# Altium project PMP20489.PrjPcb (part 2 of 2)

## Sheet PMP20489_outputs_dynLoad_Bias_HDWR.SchDoc
size 431 x 279 mm; Date: Not shown in title block; ApprovedBy: Not shown in title block; CheckedBy: Not shown in title block; Author: Not shown in title block; CompanyName: Not shown in title block; Engineer: Not shown in title block; Organization: Not shown in title block; Address1: Not shown in title block; Address2: Not shown in title block; Address3: Not shown in title block; Address4: Not shown in title block; DocumentNumber: 4; Revision: Use project parameter SCH_Rev; SheetNumber: 4; SheetTotal: 4; PageSetup: Record=PageOptions¦CenterHorizontal=True¦CenterVertical=True¦PrintScale=1.00¦XCorrection=1.00¦YCorrection=1.00¦PrintKind=0¦BorderSize=5000000¦LeftOffset=0¦BottomOffset=0¦Orientation=2¦PaperLength=1000¦PaperWidth=1000¦Scale=100¦PaperSource=15¦PrintQuality=600¦MediaType=1¦DitherType=10¦PaperKind=Letter¦PrintScaleMode=1
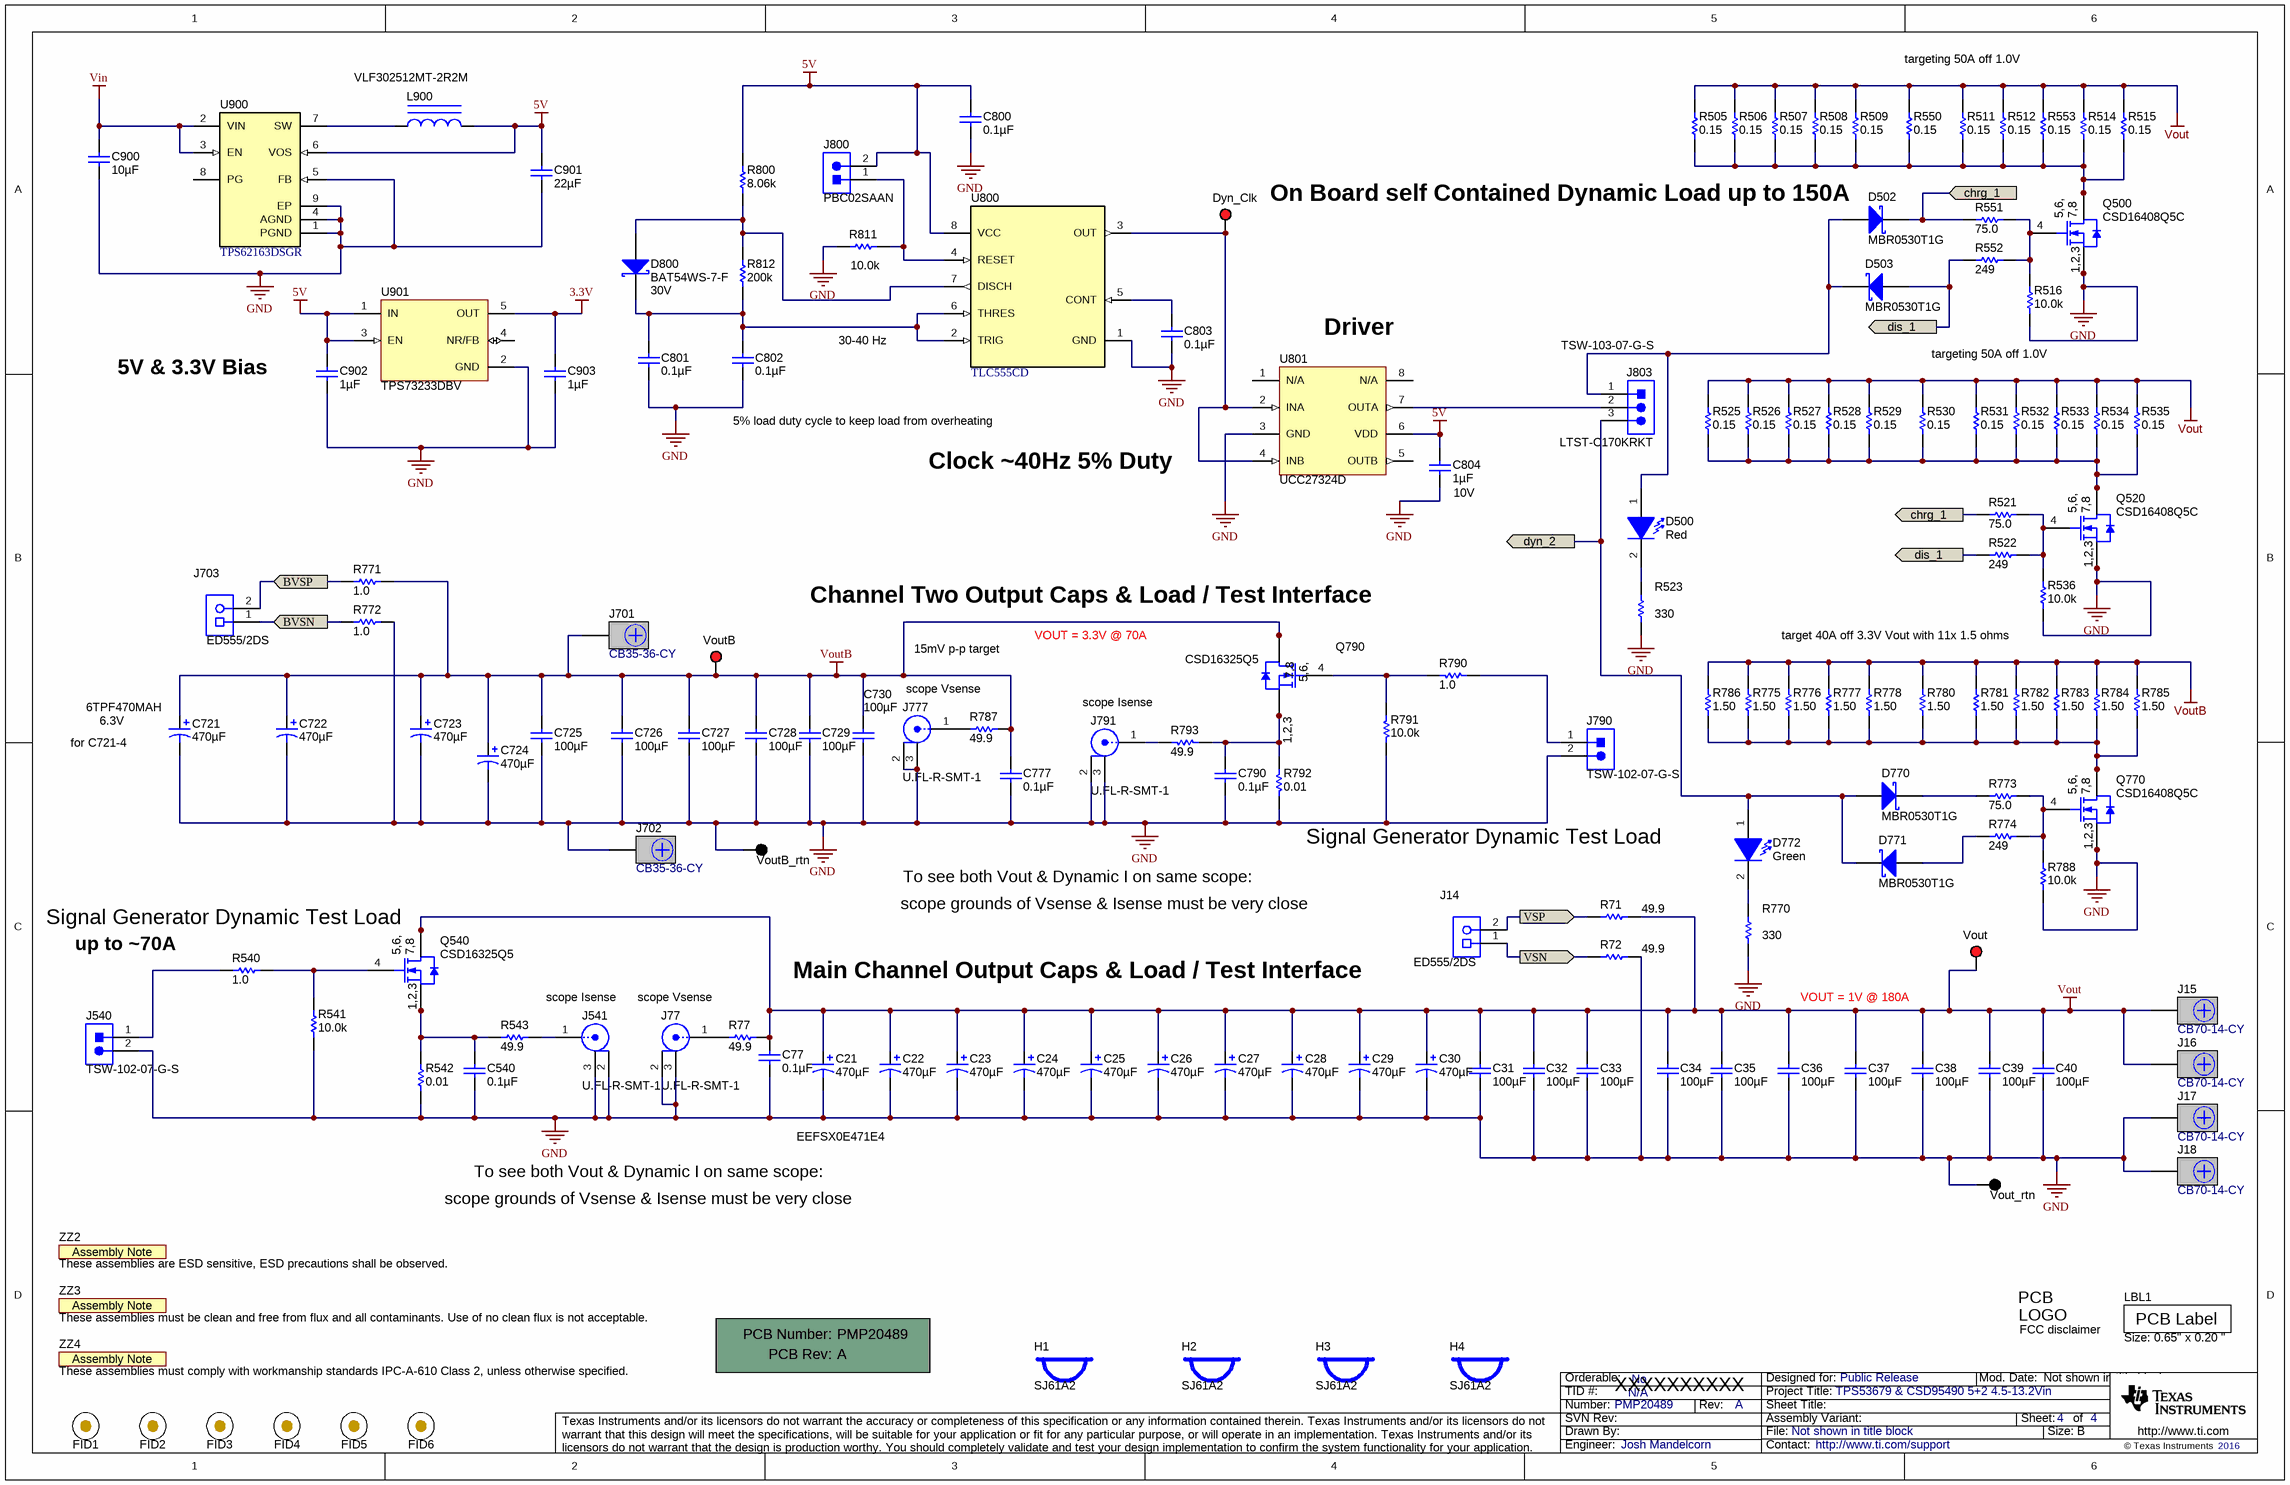
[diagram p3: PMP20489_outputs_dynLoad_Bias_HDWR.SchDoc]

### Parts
!PCB1  Printed Circuit Board  (value not drawn)  (mechanical)
C21  EEFSX0E471E4  ValueDisplayed: 470µF  [SP-Cap_Standard]
C22  ValueDisplayed: 470µF  [SP-Cap_Standard]  (hidden comment: EEFSX0E471E4)
C23  ValueDisplayed: 470µF  [SP-Cap_Standard]  (hidden comment: EEFSX0E471E4)
C24  ValueDisplayed: 470µF  [SP-Cap_Standard]  (hidden comment: EEFSX0E471E4)
C25  ValueDisplayed: 470µF  [SP-Cap_Standard]  (hidden comment: EEFSX0E471E4)
C26  ValueDisplayed: 470µF  [SP-Cap_Standard]  (hidden comment: EEFSX0E471E4)
C27  ValueDisplayed: 470µF  [SP-Cap_Standard]  (hidden comment: EEFSX0E471E4)
C28  ValueDisplayed: 470µF  [SP-Cap_Standard]  (hidden comment: EEFSX0E471E4)
C29  ValueDisplayed: 470µF  [SP-Cap_Standard]  (hidden comment: EEFSX0E471E4)
C30  ValueDisplayed: 470µF  [SP-Cap_Standard]  (hidden comment: EEFSX0E471E4)
C31  ValueDisplayed: 100µF  [1210_280]  (hidden comment: C1210C107M9PACTU)
C32  ValueDisplayed: 100µF  [1210_280]  (hidden comment: C1210C107M9PACTU)
C33  ValueDisplayed: 100µF  [1210_280]  (hidden comment: C1210C107M9PACTU)
C34  ValueDisplayed: 100µF  [1210_280]  (hidden comment: C1210C107M9PACTU)
C35  ValueDisplayed: 100µF  [1210_280]  (hidden comment: C1210C107M9PACTU)
C36  ValueDisplayed: 100µF  [1210_280]  (hidden comment: C1210C107M9PACTU)
C37  ValueDisplayed: 100µF  [1210_280]  (hidden comment: C1210C107M9PACTU)
C38  ValueDisplayed: 100µF  [1210_280]  (hidden comment: C1210C107M9PACTU)
C39  ValueDisplayed: 100µF  [1210_280]  (hidden comment: C1210C107M9PACTU)
C40  ValueDisplayed: 100µF  [1210_280]  (hidden comment: C1210C107M9PACTU)
C77  ValueDisplayed: 0.1µF  [0402]  (hidden comment: GRM155R61E104KA87D)
C540  ValueDisplayed: 0.1µF  [0402]  (hidden comment: GRM155R61E104KA87D)
C721  ValueDisplayed: 470µF  Value2: 6.3V  [7343-40]  (hidden comment: 6TPF470MAH)
C722  ValueDisplayed: 470µF  [7343-40]  (hidden comment: 6TPF470MAH)
C723  ValueDisplayed: 470µF  [7343-40]  (hidden comment: 6TPF470MAH)
C724  ValueDisplayed: 470µF  [7343-40]  (hidden comment: 6TPF470MAH)
C725  ValueDisplayed: 100µF  [1210_280]  (hidden comment: C1210C107M9PACTU)
C726  ValueDisplayed: 100µF  [1210_280]  (hidden comment: C1210C107M9PACTU)
C727  ValueDisplayed: 100µF  [1210_280]  (hidden comment: C1210C107M9PACTU)
C728  ValueDisplayed: 100µF  [1210_280]  (hidden comment: C1210C107M9PACTU)
C729  ValueDisplayed: 100µF  [1210_280]  (hidden comment: C1210C107M9PACTU)
C730  ValueDisplayed: 100µF  [1210_280]  (hidden comment: C1210C107M9PACTU)
C777  ValueDisplayed: 0.1µF  [0402]  (hidden comment: GRM155R61E104KA87D)
C790  ValueDisplayed: 0.1µF  [0402]  (hidden comment: GRM155R61E104KA87D)
C800  ValueDisplayed: 0.1µF  [0402]  (hidden comment: C1005X7R1H104M)
C801  ValueDisplayed: 0.1µF  [0402]  (hidden comment: C1005X7R1H104M)
C802  ValueDisplayed: 0.1µF  [0402]  (hidden comment: C1005X7R1H104M)
C803  ValueDisplayed: 0.1µF  [0402]  (hidden comment: C1005X7R1H104M)
C804  ValueDisplayed: 1µF  Value2: 10V  [0402]  (hidden comment: GRM155R61A105KE15D)
C900  ValueDisplayed: 10µF  [1206_180]  (hidden comment: GRM31CR61E106KA12L)
C901  ValueDisplayed: 22µF  [1206_180]  (hidden comment: GRM31CR60J226KE19L)
C902  ValueDisplayed: 1µF  [0603]  (hidden comment: C1608X5R1E105K080AC)
C903  ValueDisplayed: 1µF  [0603]  (hidden comment: C1608X5R1E105K080AC)
D500  LTST-C170KRKT  value Red  [LED_LTST-C170_Red]
D502  MBR0530T1G  [SOD-123]
D503  MBR0530T1G  [SOD-123]
D770  MBR0530T1G  [SOD-123]
D771  MBR0530T1G  [SOD-123]
D772  value Green  [LTST-C170KGKT_Green]  (hidden comment: LTST-C170KGKT)
D800  BAT54WS-7-F  value 30V  [SOD-323]
Dyn_Clk  5000  [Keystone5000]  (value not drawn)
FID1  Fiducial  [Fiducial10-30]  (value not drawn)
FID2  Fiducial  [Fiducial10-30]  (value not drawn)
FID3  Fiducial  [Fiducial10-30]  (value not drawn)
FID4  Fiducial  [Fiducial10-30]  (value not drawn)
FID5  Fiducial  [Fiducial10-30]  (value not drawn)
FID6  Fiducial  [Fiducial10-30]  (value not drawn)
H1  SJ61A2  [Bumpon_SJ61A2]
H2  SJ61A2  [Bumpon_SJ61A2]
H3  SJ61A2  [Bumpon_SJ61A2]
H4  SJ61A2  [Bumpon_SJ61A2]
J14  ED555/2DS  [TERM_BLK_ED555-2DS]
J15  CB70-14-CY  [CB70-14-CY]
J16  CB70-14-CY  [CB70-14-CY]
J17  CB70-14-CY  [CB70-14-CY]
J18  CB70-14-CY  [CB70-14-CY]
J77  U.FL-R-SMT-1  [CONN_UFL-R-SMT-1]
J540  TSW-102-07-G-S  [TSW-102-07-G-S]
J541  U.FL-R-SMT-1  [CONN_UFL-R-SMT-1]
J701  CB35-36-CY  [CB35-36-CY]
J702  CB35-36-CY  [CB35-36-CY]
J703  ED555/2DS  [TERM_BLK_ED555-2DS]
J777  U.FL-R-SMT-1  [CONN_UFL-R-SMT-1]
J790  TSW-102-07-G-S  [TSW-102-07-G-S]
J791  U.FL-R-SMT-1  [CONN_UFL-R-SMT-1]
J800  PBC02SAAN  [Sullins_PBC02SAAN]
J803  TSW-103-07-G-S  [TSW-103-07-G-S]
L900  VLF302512MT-2R2M  [VLF302512MT]
LBL1  Size: 0.65" x 0.20 "  [Label_650x200]
Logo3  FCC disclaimer  [FCC_disclaimer]  (no BOM)
Q500  CSD16408Q5C  [TRANS_NexFET_Q5C]
Q520  CSD16408Q5C  [TRANS_NexFET_Q5C]
Q540  CSD16325Q5  [TRANS_NexFET_Q5]
Q770  CSD16408Q5C  [TRANS_NexFET_Q5C]
Q790  CSD16325Q5  [TRANS_NexFET_Q5]
R71  ValueDisplayed: 49.9  [0402]  (hidden comment: CRCW040249R9FKED)
R72  ValueDisplayed: 49.9  [0402]  (hidden comment: CRCW040249R9FKED)
R77  ValueDisplayed: 49.9  [0402]  (hidden comment: CRCW040249R9FKED)
R505  ValueDisplayed: 0.15  [2512]  (hidden comment: CSRN2512FKR150)
R506  ValueDisplayed: 0.15  [2512]  (hidden comment: CSRN2512FKR150)
R507  ValueDisplayed: 0.15  [2512]  (hidden comment: CSRN2512FKR150)
R508  ValueDisplayed: 0.15  [2512]  (hidden comment: CSRN2512FKR150)
R509  ValueDisplayed: 0.15  [2512]  (hidden comment: CSRN2512FKR150)
R511  ValueDisplayed: 0.15  [2512]  (hidden comment: CSRN2512FKR150)
R512  ValueDisplayed: 0.15  [2512]  (hidden comment: CSRN2512FKR150)
R514  ValueDisplayed: 0.15  [2512]  (hidden comment: CSRN2512FKR150)
R515  ValueDisplayed: 0.15  [2512]  (hidden comment: CSRN2512FKR150)
R516  ValueDisplayed: 10.0k  [0402]  (hidden comment: CRCW040210K0FKED)
R521  ValueDisplayed: 75.0  [0603]  (hidden comment: CRCW060375R0FKEA)
R522  ValueDisplayed: 249  [0603]  (hidden comment: CRCW0603249RFKEA)
R523  ValueDisplayed: 330  [0402]  (hidden comment: CRCW0402330RJNED)
R525  ValueDisplayed: 0.15  [2512]  (hidden comment: CSRN2512FKR150)
R526  ValueDisplayed: 0.15  [2512]  (hidden comment: CSRN2512FKR150)
R527  ValueDisplayed: 0.15  [2512]  (hidden comment: CSRN2512FKR150)
R528  ValueDisplayed: 0.15  [2512]  (hidden comment: CSRN2512FKR150)
R529  ValueDisplayed: 0.15  [2512]  (hidden comment: CSRN2512FKR150)
R530  ValueDisplayed: 0.15  [2512]  (hidden comment: CSRN2512FKR150)
R531  ValueDisplayed: 0.15  [2512]  (hidden comment: CSRN2512FKR150)
R532  ValueDisplayed: 0.15  [2512]  (hidden comment: CSRN2512FKR150)
R533  ValueDisplayed: 0.15  [2512]  (hidden comment: CSRN2512FKR150)
R534  ValueDisplayed: 0.15  [2512]  (hidden comment: CSRN2512FKR150)
R535  ValueDisplayed: 0.15  [2512]  (hidden comment: CSRN2512FKR150)
R536  ValueDisplayed: 10.0k  [0402]  (hidden comment: CRCW040210K0FKED)
R540  ValueDisplayed: 1.0  [0402]  (hidden comment: CRCW04021R00JNED)
R541  ValueDisplayed: 10.0k  [0402]  (hidden comment: CRCW040210K0FKED)
R542  ValueDisplayed: 0.01  [2512]  (hidden comment: ERJ-M1WSF10MU)
R543  ValueDisplayed: 49.9  [0402]  (hidden comment: CRCW040249R9FKED)
R550  ValueDisplayed: 0.15  [2512]  (hidden comment: CSRN2512FKR150)
R551  ValueDisplayed: 75.0  [0603]  (hidden comment: CRCW060375R0FKEA)
R552  ValueDisplayed: 249  [0603]  (hidden comment: CRCW0603249RFKEA)
R553  ValueDisplayed: 0.15  [2512]  (hidden comment: CSRN2512FKR150)
R770  ValueDisplayed: 330  [0402]  (hidden comment: CRCW0402330RJNED)
R771  ValueDisplayed: 1.0  [0402]  (hidden comment: CRCW04021R00JNED)
R772  ValueDisplayed: 1.0  [0402]  (hidden comment: CRCW04021R00JNED)
R773  ValueDisplayed: 75.0  [0603]  (hidden comment: CRCW060375R0FKEA)
R774  ValueDisplayed: 249  [0603]  (hidden comment: CRCW0603249RFKEA)
R775  ValueDisplayed: 1.50  [2512]  (hidden comment: ERJ-1TRQF1R5U)
R776  ValueDisplayed: 1.50  [2512]  (hidden comment: ERJ-1TRQF1R5U)
R777  ValueDisplayed: 1.50  [2512]  (hidden comment: ERJ-1TRQF1R5U)
R778  ValueDisplayed: 1.50  [2512]  (hidden comment: ERJ-1TRQF1R5U)
R780  ValueDisplayed: 1.50  [2512]  (hidden comment: ERJ-1TRQF1R5U)
R781  ValueDisplayed: 1.50  [2512]  (hidden comment: ERJ-1TRQF1R5U)
R782  ValueDisplayed: 1.50  [2512]  (hidden comment: ERJ-1TRQF1R5U)
R783  ValueDisplayed: 1.50  [2512]  (hidden comment: ERJ-1TRQF1R5U)
R784  ValueDisplayed: 1.50  [2512]  (hidden comment: ERJ-1TRQF1R5U)
R785  ValueDisplayed: 1.50  [2512]  (hidden comment: ERJ-1TRQF1R5U)
R786  ValueDisplayed: 1.50  [2512]  (hidden comment: ERJ-1TRQF1R5U)
R787  ValueDisplayed: 49.9  [0402]  (hidden comment: CRCW040249R9FKED)
R788  ValueDisplayed: 10.0k  [0402]  (hidden comment: CRCW040210K0FKED)
R790  ValueDisplayed: 1.0  [0402]  (hidden comment: CRCW04021R00JNED)
R791  ValueDisplayed: 10.0k  [0402]  (hidden comment: CRCW040210K0FKED)
R792  ValueDisplayed: 0.01  [2512]  (hidden comment: ERJ-M1WSF10MU)
R793  ValueDisplayed: 49.9  [0402]  (hidden comment: CRCW040249R9FKED)
R800  value 8.06k  [0402]  (hidden comment: CRCW04028K06FKED)
R811  ValueDisplayed: 10.0k  [0402]  (hidden comment: CRCW040210K0FKED)
R812  value 200k  [0402]  (hidden comment: CRCW0402200KFKED)
U800  TLC555CD  [D0008A_N]
U801  UCC27324D  [D0008A_N]
U900  TPS62163DSGR  [DSG0008A]
U901  TPS73233DBV  [DBV0005A_N]
Vout  5000  [Keystone5000]  (value not drawn)
Vout_rtn  5001  [Keystone5001]  (value not drawn)
VoutB  5000  [Keystone5000]  (value not drawn)
VoutB_rtn  5001  [Keystone5001]  (value not drawn)
ZZ2  These assemblies are ESD sensitive, ESD precautions shall be observed.  [AssemblyNote]  (no BOM)
ZZ3  These assemblies must be clean and free from flux and all contaminants. Use of no clean flux is not acceptable.  [AssemblyNote]  (no BOM)
ZZ4  These assemblies must comply with workmanship standards IPC-A-610 Class 2, unless otherwise specified.  [AssemblyNote]  (no BOM)

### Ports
BVSN (in), BVSP (in), chrg_1, dis_1, dyn_2, VSN (out), VSP (out)

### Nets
3.3V: C903.2 U901.5(OUT)
5V: C800.1 C804.1 C901.1 C902.2 J800.2 L900.2 R800.2 U800.8(VCC) U801.6(VDD) U900.6(VOS) U901.1(IN) U901.3(EN)
GND: C21.2(-) C22.2(-) C23.2(-) C24.2(-) C25.2(-) C26.2(-) C27.2(-) C28.2(-) C29.2(-) C30.2(-) C31.2 C32.2 C33.2 C34.2 C35.2 C36.2 C37.2 C38.2 C39.2 C40.2 C77.2 C540.2 C721.2(-) C722.2(-) C723.2(-) C724.2(-) C725.2 C726.2 C727.2 C728.2 C729.2 C730.2 C777.2 C790.2 C800.2 C801.2 C802.2 C803.2 C804.2 C900.2 C901.2 C902.1 C903.1 J17.1 J18.1 J77.2 J77.3 J540.2 J541.2 J541.3 J702.1 J777.2 J777.3 J790.2 J791.2 J791.3 Q500.1(S) Q500.2(S) Q500.3(S) Q520.1(S) Q520.2(S) Q520.3(S) Q770.1(S) Q770.2(S) Q770.3(S) R72.2 R516.1 R523.1 R536.1 R541.1 R542.1 R770.1 R772.2 R788.1 R791.1 R792.1 R811.1 U800.1(GND) U801.3(GND) U900.1(PGND) U900.4(AGND) U900.5(FB) U900.9(EP) U901.2(GND) Vout_rtn.1 VoutB_rtn.1
Vin: C900.1 U900.2(VIN) U900.3(EN)
Vout: C21.1(+) C22.1(+) C23.1(+) C24.1(+) C25.1(+) C26.1(+) C27.1(+) C28.1(+) C29.1(+) C30.1(+) C31.1 C32.1 C33.1 C34.1 C35.1 C36.1 C37.1 C38.1 C39.1 C40.1 C77.1 J15.1 J16.1 Q540.5(D) Q540.6(D) Q540.7(D) Q540.8(D) Q540.9(D) R71.2 R77.2 R505.2 R506.2 R507.2 R508.2 R509.2 R511.2 R512.2 R514.2 R515.2 R525.2 R526.2 R527.2 R528.2 R529.2 R530.2 R531.2 R532.2 R533.2 R534.2 R535.2 R550.2 R553.2 Vout.1
VoutB: C721.1(+) C722.1(+) C723.1(+) C724.1(+) C725.1 C726.1 C727.1 C728.1 C729.1 C730.1 C777.1 J701.1 Q790.5(D) Q790.6(D) Q790.7(D) Q790.8(D) Q790.9(D) R771.2 R775.2 R776.2 R777.2 R778.2 R780.2 R781.2 R782.2 R783.2 R784.2 R785.2 R786.2 R787.2 VoutB.1
BVSN: J703.1 R772.1 ; port BVSN
BVSP: J703.2 R771.1 ; port BVSP
chrg_1: D502.1(K) R521.1 R551.1 ; port chrg_1
dis_1: D503.2(A) R522.1 R552.1 ; port dis_1
dyn_2: D770.2(A) D771.1(K) D772.1(A) J803.3 ; port dyn_2
VSN: J14.1 R72.1 ; port VSN
VSP: J14.2 R71.1 ; port VSP
NetC540_1: C540.1 Q540.1(S) Q540.2(S) Q540.3(S) R542.2 R543.1
NetC790_1: C790.1 Q790.1(S) Q790.2(S) Q790.3(S) R792.2 R793.1
NetC801_1: C801.1 C802.1 D800.1(K) R812.1 U800.2(TRIG) U800.6(THRES)
NetC803_1: C803.1 U800.5(CONT)
NetD500_1: D500.1(A) D502.2(A) D503.1(K) J803.1
NetD500_2: D500.2(K) R523.2
NetD770_1: D770.1(K) R773.1
NetD771_2: D771.2(A) R774.1
NetD772_2: D772.2(K) R770.2
NetD800_2: D800.2(A) R800.1 R812.2 U800.7(DISCH)
NetDyn_Clk_1: Dyn_Clk.1 U800.3(OUT) U801.2(INA) U801.4(INB)
NetJ77_1: J77.1 R77.1
NetJ540_1: J540.1 R540.1
NetJ541_1: J541.1 R543.2
NetJ777_1: J777.1 R787.1
NetJ790_1: J790.1 R790.1
NetJ791_1: J791.1 R793.2
NetJ800_1: J800.1 R811.2 U800.4(RESET)
NetJ803_2: J803.2 U801.7(OUTA)
NetL900_1: L900.1 U900.7(SW)
NetQ500_4: Q500.4(G) R516.2 R551.2 R552.2
NetQ500_5: Q500.5(D) Q500.6(D) Q500.7(D) Q500.8(D) Q500.10(D) R505.1 R506.1 R507.1 R508.1 R509.1 R511.1 R512.1 R514.1 R515.1 R550.1 R553.1
NetQ520_4: Q520.4(G) R521.2 R522.2 R536.2
NetQ520_5: Q520.5(D) Q520.6(D) Q520.7(D) Q520.8(D) Q520.10(D) R525.1 R526.1 R527.1 R528.1 R529.1 R530.1 R531.1 R532.1 R533.1 R534.1 R535.1
NetQ540_4: Q540.4(G) R540.2 R541.2
NetQ770_4: Q770.4(G) R773.2 R774.2 R788.2
NetQ770_5: Q770.5(D) Q770.6(D) Q770.7(D) Q770.8(D) Q770.10(D) R775.1 R776.1 R777.1 R778.1 R780.1 R781.1 R782.1 R783.1 R784.1 R785.1 R786.1
NetQ790_4: Q790.4(G) R790.2 R791.2

Not connected (* = marked no-connect by the designer): U801 1(N/A) 5(OUTB) 8(N/A); U900 8(PG); U901 4(NR/FB)

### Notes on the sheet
- targeting 50A off 1.0V
- On Board self Contained Dynamic Load up to 150A
- 5V & 3.3V Bias
- 30-40 Hz
- (near U801) Driver
- 5% load duty cycle to keep load from overheating
- Clock ~40Hz 5% Duty
- Channel Two Output Caps & Load / Test Interface
- VOUT = 3.3V @ 70A
- target 40A off 3.3V Vout with 11x 1.5 ohms
- scope Vsense
- 15mV p-p target
- scope Isense
- (near C721) for C721-4
- (near R792) Signal Generator Dynamic Test Load
- To see both Vout & Dynamic I on same scope:
- scope grounds of Vsense & Isense must be very close
- Signal Generator Dynamic Test Load
- up to ~70A
- Main Channel Output Caps & Load / Test Interface
- VOUT = 1V @ 180A
- XXXXXXXXXX

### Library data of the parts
!PCB1 = PCB: Manufacturer: Any; PartNumber: PMP20489; SymbolCreator: a0412235
C21-C30 = EEFSX0E471E4: CAP, Aluminum Polymer, 470 µF, 2.5 V, +/- 20%, 4.5 ohm, 7.3x1.8x4.3mm SMD; Manufacturer: Panasonic; Polarized: Y; CompType: Capacitor; Value: 470uF; U/M: EA; Cap_F: 0.00047; Tolerance_%: 20; Value1: 4.5 ohm; VDC_V: 2.5; Value2: 2.5V; ESR_ohm: 4.5; IRMS_A: 3; TaMin_C: -40; TaMax_C: 105; AEC Category: Q200
C31-C40 C725-C730 = C1210C107M9PACTU: CAP, CERM, 100 µF, 6.3 V, +/- 20%, X5R, 1210; Manufacturer: Kemet; Polarized: N; CompType: Capacitor; Value: 100uF; U/M: EA; Cap_F: 0.0001; Tolerance_%: 20; Value1: Unknown; VDC_V: 6.3; Value2: 6.3V; TaMin_C: -55; TaMax_C: 85; Cap_Case: 1210; SizeArea_mm2: 8; SizeAreaWB_mm2: 14.7; SizeX_mm: 3.2; SizeY_mm: 2.5; SizeZ_mm: 2.8; AEC Category: Q200
C77 C777 = GRM155R61E104KA87D: CAP, CERM, 0.1 µF, 25 V, +/- 10%, X5R, 0402; Manufacturer: MuRata; Polarized: N; CompType: Capacitor; Value: 0.1uF; U/M: EA; Cap_F: 0.0000001; Tolerance_%: 10; Value1: Unknown; VDC_V: 25; Value2: 25V; TaMin_C: -55; TaMax_C: 85; SizeArea_mm2: 0.5; SizeAreaWB_mm2: 3; SizeX_mm: 1; SizeZ_mm: 0.6; AEC Category: Q200
C540 C790 = GRM155R61E104KA87D: CAP, CERM, 0.1 µF, 25 V, +/- 10%, X5R, 0402; Manufacturer: MuRata; Polarized: N; CompType: Capacitor; Value: 0.1uF; U/M: EA; Cap_F: 0.0000001; Tolerance_%: 10; Value1: Unknown; VDC_V: 25; Value2: 25V; TaMin_C: -55; TaMax_C: 85; AEC Category: Q200; SizeArea_mm2: 0.5; SizeAreaWB_mm2: 3; SizeX_mm: 1; SizeZ_mm: 0.6
C721 = 6TPF470MAH: CAP, Tantalum Polymer, 470 µF, 6.3 V, +/- 20%, 0.01 ohm, 7343-40 SMD; Manufacturer: Panasonic; Polarized: Y; CompType: Capacitor; Value: 470uF; U/M: EA; Cap_F: 0.00047; Tolerance_%: 20; VDC_V: 6.3; ESR_ohm: 0.01; IRMS_A: 4.4; TaMin_C: -55; TaMax_C: 105; Cap_Case: D4; AEC Category: Q200; AEC Qualified: N; SizeAreaWB_mm2: 58.59; SizeArea_mm2: 31.39; SizeX_mm: 7.3; SizeY_mm: 4.3; SizeZ_mm: 4
C722-C724 = 6TPF470MAH: CAP, Tantalum Polymer, 470 µF, 6.3 V, +/- 20%, 0.01 ohm, 7343-40 SMD; Manufacturer: Panasonic; Polarized: Y; CompType: Capacitor; Value: 470uF; U/M: EA; Cap_F: 0.00047; Tolerance_%: 20; VDC_V: 6.3; Value2: 6.3V; ESR_ohm: 0.01; IRMS_A: 4.4; TaMin_C: -55; TaMax_C: 105; Cap_Case: D4; AEC Category: Q200; AEC Qualified: N; SizeAreaWB_mm2: 58.59; SizeArea_mm2: 31.39; SizeX_mm: 7.3; SizeY_mm: 4.3; SizeZ_mm: 4
C800-C803 = C1005X7R1H104M: CAP, CERM, 0.1 µF, 50 V, +/- 20%, X7R, 0402; Manufacturer: TDK; Polarized: N; CompType: Capacitor; Value: 0.1uF; U/M: EA; Cap_F: 0.0000001; Tolerance_%: 20; Value1: Unknown; VDC_V: 50; Value2: 50V; TaMin_C: -55; TaMax_C: 125
C804 = GRM155R61A105KE15D: CAP, CERM, 1 µF, 10 V, +/- 10%, X5R, 0402; Manufacturer: MuRata; Polarized: N; CompType: Capacitor; Value: 1uF; U/M: EA; Cap_F: 0.000001; Tolerance_%: 10; Value1: Unknown; TaMin_C: -55; TaMax_C: 85; SizeArea_mm2: 0.5; SizeAreaWB_mm2: 3; SizeX_mm: 1; SizeZ_mm: 0.6; AEC Category: Q200
C900 = GRM31CR61E106KA12L: CAP, CERM, 10 µF, 25 V, +/- 10%, X5R, 1206; Manufacturer: MuRata; Polarized: N; CompType: Capacitor; Value: 10uF; U/M: EA; Cap_F: 0.00001; Tolerance_%: 10; ESR_ohm: 0.004; Value1: 0.004 ohm; VDC_V: 25; Value2: 25V; TaMin_C: -55; TaMax_C: 85; Cap_Case: 1206; SizeArea_mm2: 5.12; SizeAreaWB_mm2: 10.92; SizeX_mm: 3.2; SizeY_mm: 1.6; SizeZ_mm: 1.8; AEC Category: Q200
C901 = GRM31CR60J226KE19L: CAP, CERM, 22 µF, 6.3 V, +/- 10%, X5R, 1206; Manufacturer: MuRata; Polarized: N; CompType: Capacitor; Value: 22uF; U/M: EA; Cap_F: 0.000022; Tolerance_%: 10; ESR_ohm: 0.003; Value1: 0.003 ohm; VDC_V: 6.3; Value2: 6.3V; TaMin_C: -55; TaMax_C: 85; Cap_Case: 1206; SizeArea_mm2: 5.12; SizeAreaWB_mm2: 10.92; SizeX_mm: 3.2; SizeY_mm: 1.6; SizeZ_mm: 1.8; AEC Category: Q200
C902 C903 = C1608X5R1E105K080AC: CAP, CERM, 1 µF, 25 V, +/- 10%, X5R, 0603; Manufacturer: TDK; Polarized: N; CompType: Capacitor; Value: 1uF; U/M: EA; Cap_F: 0.000001; Tolerance_%: 10; Value1: Unknown; VDC_V: 25; Value2: 25V; TaMin_C: -55; TaMax_C: 85; SizeArea_mm2: 1.28; SizeAreaWB_mm2: 4.68; SizeX_mm: 1.6; SizeY_mm: 0.8; SizeZ_mm: 1; AEC Category: Q200
D500 = LTST-C170KRKT: LED, Red, SMD; Manufacturer: Lite-On; Type: AlInGaP; Vf_V: 2; Value2: 2V; Io_A: 0.02; Value1: W; U/M: EA; SizeAreaWB_mm2: 6.75; SizeArea_mm2: 2.5; SizeY_mm: 1.25; SizeZ_mm: 1.2
D502 D503 D770 D771 = MBR0530T1G: Diode, Schottky, 30 V, 0.5 A, SOD-123; Manufacturer: ON Semiconductor; Value: 30V; U/M: EA; Vf_V: 0.43; Value1: 0.5A; Value2: 0.43V; Io_A: 0.5; Vr_V: 30; TJmax_C: 125; RJC_CperW: 150; SizeAreaWB_mm2: 13.095; SizeArea_mm2: 6.545; SizeX_mm: 3.85; SizeY_mm: 1.7; SizeZ_mm: 1.35; AEC Category: Q101
D772 = LTST-C170KGKT: LED, Green, SMD; Manufacturer: Lite-On; Type: AlInGaP; Vf_V: 2; Value2: 2V; Io_A: 0.02; Value1: W; U/M: EA
D800 = BAT54WS-7-F: Diode, Schottky, 30 V, 0.2 A, SOD-323; Manufacturer: Diodes Inc.; U/M: EA; Vf_V: 0.7; Value1: 0.2A; Value2: 0.7V; Io_A: 0.2; Vr_V: 30; TJmax_C: 125; SizeAreaWB_mm2: 8.695; SizeArea_mm2: 3.645; SizeX_mm: 2.7; SizeY_mm: 1.35; SizeZ_mm: 1; AEC Category: Q101
Dyn_Clk Vout VoutB = 5000: Test Point, Miniature, Red, TH; Manufacturer: Keystone; CompType: Test Point Loop; ContactFinish: Silver
FID1-FID6 = Fiducial: Fiducial mark.  There is nothing to buy or mount.; SymbolCreator: codlsc
H1-H4 = SJ61A2: Bumpon, Hemisphere, 0.375 X 0.235, Black; Manufacturer: 3M; SymbolCreator: a0412235
J14 J703 = ED555/2DS: Terminal Block, 3.5mm Pitch, 2x1, TH; Manufacturer: On-Shore Technology; SymbolCreator: a0412235; Pitch_mm: 3.5; Gender: Female; Shrouded: N; Row_Count: 1; ContactFinish: Brass; Current_A: 6; Voltage_V: 150; Cert_CULUS: Y
J15-J18 = CB70-14-CY: Terminal 90A Lug; Manufacturer: Panduit; SymbolCreator: crossc; CompType: Screw Terminal; ContactFinish: Copper; Voltage_V: 600; Cert_CULUS: Y
J77 J541 J777 J791 = U.FL-R-SMT-1: Connector, Ultra-Mini Coaxial, SMD; Manufacturer: Hirose Electric Co. Ltd.; SymbolCreator: a0412235
J540 J790 = TSW-102-07-G-S: Header, 100mil, 2x1, Gold, TH; Manufacturer: Samtec; SymbolCreator: a0412235; Pitch_mm: 2.54; Gender: Male; Shrouded: N; Row_Count: 1; Current_A: 6.3; Voltage_V: 550; Cert_CSA: Y
J701 J702 = CB35-36-CY: Terminal 50A Lug; Manufacturer: Panduit; SymbolCreator: crossc; CompType: Screw Terminal; ContactFinish: Copper; Voltage_V: 600; Cert_CULUS: Y
J800 = PBC02SAAN: Header, 100mil, 2x1, Gold, TH; Manufacturer: Sullins Connector Solutions; SymbolCreator: a0412235; Pitch_mm: 2.54; Gender: Male; Shrouded: N; Row_Count: 1; Current_A: 3; Voltage_V: 1800; Cert_UL: Y
J803 = TSW-103-07-G-S: Header, 100mil, 3x1, Gold, TH; Manufacturer: Samtec; SymbolCreator: a0799628; Pitch_mm: 2.54; Gender: Male; Shrouded: N; Row_Count: 1; Current_A: 6.3; Voltage_V: 550; Cert_CSA: Y
L900 = VLF302512MT-2R2M: Inductor, Shielded, Ferrite, 2.2 µH, 1.26 A, 0.066 ohm, SMD; Manufacturer: TDK; Value: 2.2uH; Ind_H: 2.2E-6; ValueDisplayed: 2.2µH; Imax_A: 1.26; Irms: 1.95A @ 40C rise; Isat: 1.26A @ 30% inductance drop; DCR_ohm: 0.066; Value2: 1.26A; AEC Category: Q200
LBL1 = THT-14-423-10: Thermal Transfer Printable Labels, 0.650" W x 0.200" H - 10,000 per roll; Manufacturer: Brady; SymbolCreator: a0412235; CompType: Label
Logo3 = FCC_disclaimer: SymbolCreator: a0412235
Q500 Q520 Q770 = CSD16408Q5C: MOSFET, N-CH, 25 V, 113 A, DualCool SON 5x6mm; Manufacturer: Texas Instruments; Alternate Manufacturer: None; U/M: EA; ChType: N; Value: 25V; VdsMax_V: 25; Value1: 0.0054 ohm; Rdson45_ohm: 0.0054; Value2: 6.7 nC; QgTyp_nC: 6.7; Vgs_V: 16; IdsMax_A: 113; SizeAreaWB_mm2: 56; SizeArea_mm2: 30; SizeX_mm: 6; SizeY_mm: 5; SizeZ_mm: 1; AEC Category: Q101
Q540 Q790 = CSD16325Q5: MOSFET, N-CH, 25 V, 100 A, SON 5x6mm; Manufacturer: Texas Instruments; Alternate Manufacturer: None; U/M: EA; ChType: N; Value: 25V; VdsMax_V: 25; Value1: 0.0017 ohm; Rdson45_ohm: 0.0017; Value2: 18 nC; QgTyp_nC: 18; Vgs_V: 10; IdsMax_A: 100; AEC Category: Q101; SizeAreaWB_mm2: 55.131; SizeArea_mm2: 29.351; SizeX_mm: 5.99; SizeY_mm: 4.9; SizeZ_mm: 1.12
R71 R72 R77 R787 = CRCW040249R9FKED: RES, 49.9, 1%, 0.063 W, 0402; Manufacturer: Vishay-Dale; CompType: Resistor; Value: 49.9; Value_Code: 49R9; Tolerance_%: 1; Power_W: 0.063; Value2: 0.063W; VDC_V: 50; TempCo: 100 ppm/C; EIA_Code: E96; U/M: EA; SizeArea_mm2: 0.5; SizeZ_mm: 0.6; AEC Category: Q200
R505-R509 R511 R512 R514 R515 R525-R535 R550 R553 = CSRN2512FKR150: RES, 0.15, 1%, 2 W, 2512; Manufacturer: Stackpole Electronics Inc; CompType: Resistor; Value: 0.15; Value_Code: R150; Tolerance_%: 1; Power_W: 2; Value2: 2W; TempCo: 200 ppm/C; EIA_Code: E96; U/M: EA; AEC Category: Q200; SizeArea_mm2: 20.16; SizeX_mm: 6.3; SizeY_mm: 3.2; SizeZ_mm: 0.71
R516 R536 R788 R811 = CRCW040210K0FKED: RES, 10.0 k, 1%, 0.063 W, 0402; Manufacturer: Vishay-Dale; CompType: Resistor; Value: 10.0k; Res_ohm: 10000; Value_Code: 10k0; Tolerance_%: 1; Power_W: 0.063; Value2: 0.063W; VDC_V: 50; TempCo: 100 ppm/C; EIA_Code: E96; U/M: EA; SizeArea_mm2: 0.5; SizeZ_mm: 0.6; AEC Category: Q200
R521 R551 R773 = CRCW060375R0FKEA: RES, 75.0, 1%, 0.1 W, 0603; Manufacturer: Vishay-Dale; CompType: Resistor; Value: 75.0; Res_ohm: 75; Value_Code: 75R0; Tolerance_%: 1; Power_W: 0.1; Value2: 0.1W; TempCo: 100 ppm/C; EIA_Code: E96; U/M: EA; SizeArea_mm2: 1.28; SizeX_mm: 1.6; SizeY_mm: 0.8; AEC Category: Q200
R522 R552 R774 = CRCW0603249RFKEA: RES, 249, 1%, 0.1 W, 0603; Manufacturer: Vishay-Dale; CompType: Resistor; Value: 249; Value_Code: 249R; Tolerance_%: 1; Power_W: 0.1; Value2: 0.1W; VDC_V: 75; TempCo: 100 ppm/C; EIA_Code: E96; U/M: EA; SizeArea_mm2: 1.28; SizeX_mm: 1.6; SizeY_mm: 0.8; AEC Category: Q200
R523 R770 = CRCW0402330RJNED: RES, 330, 5%, 0.063 W, 0402; Manufacturer: Vishay-Dale; CompType: Resistor; Value: 330; Value_Code: 330R; Tolerance_%: 5; Power_W: 0.063; Value2: 0.063W; VDC_V: 50; TempCo: 200 ppm/C; EIA_Code: E24; U/M: EA; SizeArea_mm2: 0.5; SizeX_mm: 1; SizeZ_mm: 0.6; AEC Category: Q200
R540 R790 = CRCW04021R00JNED: RES, 1.0, 5%, 0.063 W, 0402; Manufacturer: Vishay-Dale; CompType: Resistor; Value: 1.0; Res_ohm: 1; Value_Code: 1R00; Tolerance_%: 5; Power_W: 0.063; Value2: 0.063W; VDC_V: 50; TempCo: 200 ppm/C; EIA_Code: E24; U/M: EA; AEC Category: Q200; SizeArea_mm2: 0.5; SizeZ_mm: 0.6
R541 R791 = CRCW040210K0FKED: RES, 10.0 k, 1%, 0.063 W, 0402; Manufacturer: Vishay-Dale; CompType: Resistor; Value: 10.0k; Res_ohm: 10000; Value_Code: 10k0; Tolerance_%: 1; Power_W: 0.063; Value2: 0.063W; VDC_V: 50; TempCo: 100 ppm/C; EIA_Code: E96; U/M: EA; AEC Category: Q200; SizeArea_mm2: 0.5; SizeZ_mm: 0.6
R542 R792 = ERJ-M1WSF10MU: RES, 0.01, 1%, 1 W, 2512; Manufacturer: Panasonic; CompType: Resistor; Value: 0.01; Value_Code: R010; Tolerance_%: 1; Value2: 1W; TempCo: 100 ppm/C; EIA_Code: E96; U/M: EA; AEC Category: Q200; SizeArea_mm2: 20.16; SizeX_mm: 6.3; SizeY_mm: 3.2; SizeZ_mm: 0.71
R543 R793 = CRCW040249R9FKED: RES, 49.9, 1%, 0.063 W, 0402; Manufacturer: Vishay-Dale; CompType: Resistor; Value: 49.9; Value_Code: 49R9; Tolerance_%: 1; Power_W: 0.063; Value2: 0.063W; VDC_V: 50; TempCo: 100 ppm/C; EIA_Code: E96; U/M: EA; AEC Category: Q200; SizeArea_mm2: 0.5; SizeZ_mm: 0.6
R771 R772 = CRCW04021R00JNED: RES, 1.0, 5%, 0.063 W, 0402; Manufacturer: Vishay-Dale; CompType: Resistor; Value: 1.0; Res_ohm: 1; Value_Code: 1R00; Tolerance_%: 5; Power_W: 0.063; Value2: 0.063W; VDC_V: 50; TempCo: 200 ppm/C; EIA_Code: E24; U/M: EA; SizeArea_mm2: 0.5; SizeZ_mm: 0.6; AEC Category: Q200
R775-R778 R780-R786 = ERJ-1TRQF1R5U: RES, 1.50, 1%, 1 W, 2512; Manufacturer: Panasonic; CompType: Resistor; Value: 1.50; Res_ohm: 1.5; Value_Code: 1R50; Tolerance_%: 1; Value2: 1W; TempCo: 100 ppm/C; EIA_Code: E96; U/M: EA; AEC Category: Q200; SizeArea_mm2: 20.16; SizeX_mm: 6.3; SizeY_mm: 3.2; SizeZ_mm: 0.71
R800 = CRCW04028K06FKED: RES, 8.06 k, 1%, 0.063 W, 0402; Manufacturer: Vishay-Dale; CompType: Resistor; Res_ohm: 8060; Value_Code: 8k06; Tolerance_%: 1; Power_W: 0.063; Value2: 0.063W; VDC_V: 50; TempCo: 100 ppm/C; EIA_Code: E96; U/M: EA; SizeArea_mm2: 0.5; SizeZ_mm: 0.6; AEC Category: Q200
R812 = CRCW0402200KFKED: RES, 200 k, 1%, 0.063 W, 0402; Manufacturer: Vishay-Dale; CompType: Resistor; Res_ohm: 200000; Tolerance_%: 1; Power_W: 0.063; Value2: 0.063W; VDC_V: 50; TempCo: 100 ppm/C; EIA_Code: E96; U/M: EA; SizeArea_mm2: 0.5; SizeZ_mm: 0.6; AEC Category: Q200
U800 = TLC555CD: LinCMOS Timer, D0008A; Manufacturer: Texas Instruments; SymbolCreator: a0799628; SizeArea_mm2: 30.38; SizeAreaWB_mm2: 56.58; SizeX_mm: 4.9; SizeY_mm: 6.2; SizeZ_mm: 1.75; CompType: IC; U/M: EA
U801 = UCC27324D: DUAL 4-A PEAK HIGH SPEED LOW- SIDE POWER MOSFET DRIVERS, D0008A; Manufacturer: Texas Instruments; Alternate Manufacturer: None; SymbolCreator: a0412235; CompType: IC; U/M: EA
U900 = TPS62163DSGR: Buck Step Down Regulator with 3 to 17 V Input and 5 V Output, -40 to 85 degC, 8-Pin WSON (DSG), Green (RoHS & no Sb/Br); Manufacturer: Texas Instruments; Alternate PartNumber: Equivalent; Duty Cycle(Max)(%): 100; Iout(Max)(A): 1; Iq(Typ)(mA): 0.017; Preset Vout(V): 5; Rating: Catalog; SubFamily: Step-Down Regulator; Switch Current Limit(Typ)(A): 1.8; Synchronous Rectification: TRUE; Vin(Max)(V): 17; Vin(Min)(V): 3
U901 = TPS73233DBV: Cap-Free, NMOS, 250mA Low Dropout Regulator with Reverse Current Protection, DBV0005A; Alternate Manufacturer: Texas Instruments; Alternate Manufacturer: None; SymbolCreator: a0411947; CompType: IC; U/M: EA
Vout_rtn VoutB_rtn = 5001: Test Point, Miniature, Black, TH; Manufacturer: Keystone; CompType: Test Point Loop; ContactFinish: Silver
ZZ2-ZZ4 = AssemblyNote: SymbolCreator: codlsc

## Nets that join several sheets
3.3V: PMP20489_TPS53679controller&Ch2PS (5 pins), PMP20489_outputs_dynLoad_Bias_HDWR (C903.2 U901.5)
5V: PMP20489_TPS53679controller&Ch2PS (6 pins), PMP20489_MainInput&MainChPowerStages (10 pins), PMP20489_outputs_dynLoad_Bias_HDWR (12 pins)
GND: PMP20489_TPS53679controller&Ch2PS (39 pins), PMP20489_MainInput&MainChPowerStages (66 pins), PMP20489_outputs_dynLoad_Bias_HDWR (86 pins)
Vin: PMP20489_TPS53679controller&Ch2PS (14 pins), PMP20489_MainInput&MainChPowerStages (38 pins), PMP20489_outputs_dynLoad_Bias_HDWR (C900.1 U900.2 U900.3)
Vout: PMP20489_MainInput&MainChPowerStages (10 pins), PMP20489_outputs_dynLoad_Bias_HDWR (53 pins)
VoutB: PMP20489_TPS53679controller&Ch2PS (L600.2 L700.2 U600.5 U700.5), PMP20489_outputs_dynLoad_Bias_HDWR (31 pins)
A_pin11: PMP20489_TPS53679controller&Ch2PS (R2.2 R67.2), PMP20489_MainInput&MainChPowerStages (5 pins)
BVSN: PMP20489_TPS53679controller&Ch2PS (C5.1 R9.2 U1.29), PMP20489_outputs_dynLoad_Bias_HDWR (J703.1 R772.1)
BVSP: PMP20489_TPS53679controller&Ch2PS (R11.2), PMP20489_outputs_dynLoad_Bias_HDWR (J703.2 R771.1)
CSP1: PMP20489_TPS53679controller&Ch2PS (U1.4), PMP20489_MainInput&MainChPowerStages (U100.2)
CSP2: PMP20489_TPS53679controller&Ch2PS (J1.2 U1.5), PMP20489_MainInput&MainChPowerStages (U200.2)
CSP3: PMP20489_TPS53679controller&Ch2PS (J1.4 U1.6), PMP20489_MainInput&MainChPowerStages (U300.2)
CSP4: PMP20489_TPS53679controller&Ch2PS (J1.6 U1.7), PMP20489_MainInput&MainChPowerStages (U400.2)
CSP5: PMP20489_TPS53679controller&Ch2PS (J1.8 U1.8), PMP20489_MainInput&MainChPowerStages (U500.2)
CSPIN: PMP20489_TPS53679controller&Ch2PS (C3.2 C8.1 U1.12), PMP20489_MainInput&MainChPowerStages (R42.2)
PWM1: PMP20489_TPS53679controller&Ch2PS (U1.39), PMP20489_MainInput&MainChPowerStages (U100.10)
PWM2: PMP20489_TPS53679controller&Ch2PS (U1.38), PMP20489_MainInput&MainChPowerStages (U200.10)
PWM3: PMP20489_TPS53679controller&Ch2PS (U1.37), PMP20489_MainInput&MainChPowerStages (U300.10)
PWM4: PMP20489_TPS53679controller&Ch2PS (U1.36), PMP20489_MainInput&MainChPowerStages (U400.10)
PWM5: PMP20489_TPS53679controller&Ch2PS (U1.35), PMP20489_MainInput&MainChPowerStages (U500.10)
TSEN: PMP20489_TPS53679controller&Ch2PS (7 pins), PMP20489_MainInput&MainChPowerStages (10 pins)
VIN_CSNIN: PMP20489_TPS53679controller&Ch2PS (C2.1 C3.1 U1.11), PMP20489_MainInput&MainChPowerStages (R41.2)
VREF: PMP20489_TPS53679controller&Ch2PS (7 pins), PMP20489_MainInput&MainChPowerStages (10 pins)
VSN: PMP20489_TPS53679controller&Ch2PS (C60.2 U1.3), PMP20489_outputs_dynLoad_Bias_HDWR (J14.1 R72.1)
VSP: PMP20489_TPS53679controller&Ch2PS (R62.2), PMP20489_outputs_dynLoad_Bias_HDWR (J14.2 R71.1)

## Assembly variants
001: not fitted FID1 FID2 FID3 FID4 FID5 FID6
